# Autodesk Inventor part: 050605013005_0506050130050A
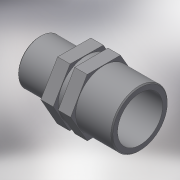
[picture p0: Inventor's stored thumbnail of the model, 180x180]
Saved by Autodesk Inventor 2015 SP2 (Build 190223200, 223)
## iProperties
Created: 2017-05
Part Number: 050605013005_0506050130050A
Material: Generic
Description: PLASSON REDUCING NIPPLE 1.1/4"-1/2"
Document SubType Name: Modeling
Designer: KIM
Density: 1 g/cm^3
Appearance: Default
Author: KIM
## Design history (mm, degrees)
derived "050605.ipt"
feature "Solid1::050605.ipt"
tag "TaggingFeature1"
body "Solid1"
other parameters: "d0" = 53, "d1" = 41.91, "d5" = 21, "d6" = 5.3, "d8" = 0.53, "d12" = 0, "d14" = 20.955, "d15" = 16.764, "d16" = 33.528, "d17" = 16, "d18" = 2.65, "d19" = 46, "d21" = 0, "H_" = 53, "R_" = 41.91, "E_" = 46, "l_" = 21, "R_1" = 20.955, "l_1" = 16
